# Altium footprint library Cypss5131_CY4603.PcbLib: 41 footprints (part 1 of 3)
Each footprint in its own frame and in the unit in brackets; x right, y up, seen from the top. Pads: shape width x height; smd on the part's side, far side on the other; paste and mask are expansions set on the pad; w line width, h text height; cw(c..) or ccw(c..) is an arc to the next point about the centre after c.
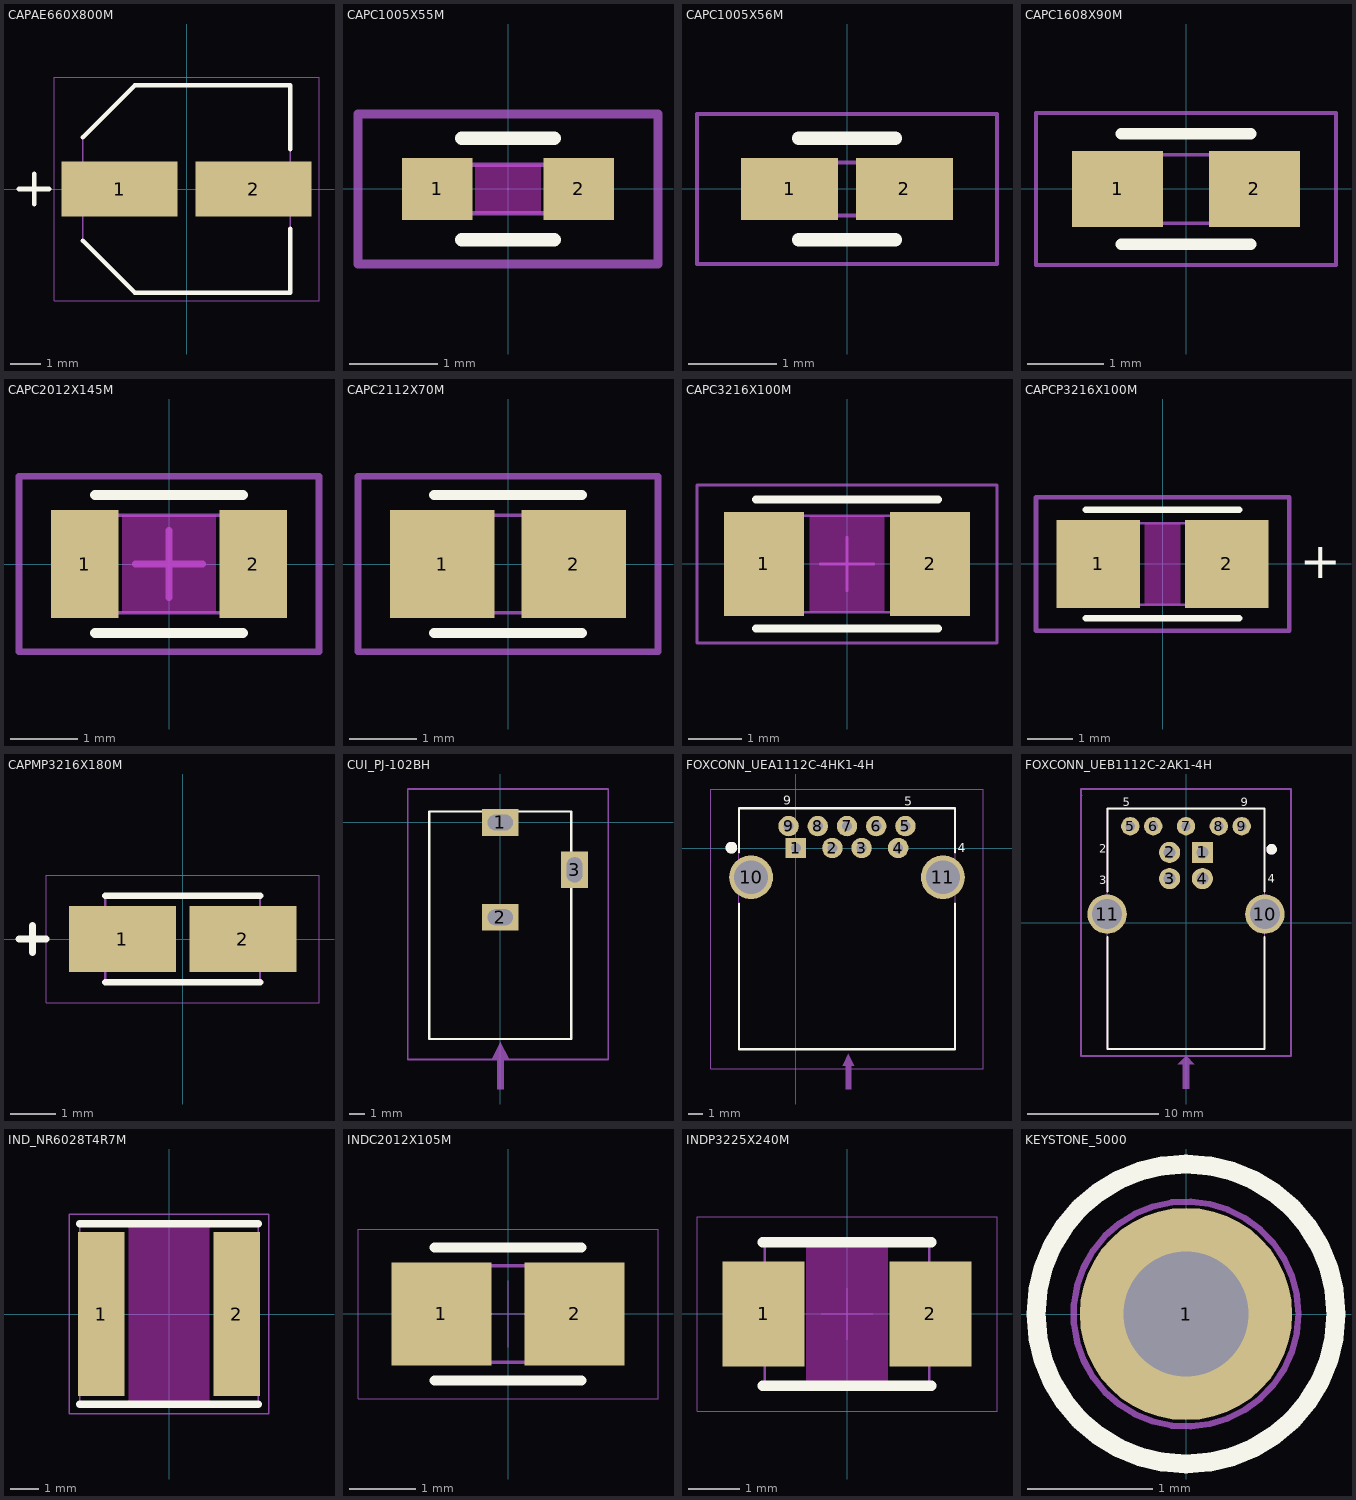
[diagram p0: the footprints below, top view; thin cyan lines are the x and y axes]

## CAPAE660X800M [mm]
height 8
pads (2):
  rect 3.8x1.8 smd mask+0: 1(-2.2,0) 2(2.2,0)
Top Overlay:
  lines w0.15: -5.5,0 -4.5,0 ; -5,-0.5 -5,0.5 ; -3.4,-1.7 -1.7,-3.4 -1.699,-3.401 3.401,-3.401 3.4,-3.4 3.4,-1.3 ; -3.4,1.7 -1.7,3.4 3.4,3.4 3.4,1.3
  text ".Designator" at -3.92,4.294 h0.8
Mechanical 13:
  lines w0.05: -3.4,-1.7 -1.7,-3.4 3.4,-3.4 3.4,3.4 -1.7,3.4 -3.4,1.7 -3.4,-1.7
  text ".Designator" at -4.142,-0.291 h0.8
Mechanical 14:
  text "R380_180" at -3.009,-5.076 h0.8
  text "CAPAE660X800M" at -5.4,5.9 h0.8
Mechanical 15:
  lines w0.01: -4.35,-3.675 -4.35,3.675 4.35,3.675 4.35,-3.675 -4.35,-3.675
3D body: height 8, standoff 0, extent -3.401,-3.401 3.401,3.401

## CAPC1005X55M [mm]
height 0.55
pads (2):
  rect 0.8x0.7 smd mask+0: 1(-0.8,0) 2(0.8,0)
Top Layer keep-out:
  rectangle: -0.375,-0.275 0.375,0.275
Top Overlay:
  lines w0.15: -0.525,-0.575 0.525,-0.575 ; -0.525,0.575 0.525,0.575
  text ".Designator" at -4.05,1.35 h0.8
Mechanical 13:
  lines w0.05: -0.525,-0.275 0.525,-0.275 0.525,0.275 -0.525,0.275 -0.525,-0.275
  text ".Designator" at -4.047,-0.16 h0.8
Mechanical 14:
  text "R80_70" at -2.25,-2 h0.8
  text "CAPC1005X55M" at -4.5,2.5 h0.8
Mechanical 15:
  lines w0.1: -1.7,-0.85 1.7,-0.85 1.7,0.85 -1.7,0.85 -1.7,-0.85
3D body: height 0.55, standoff 0, extent -0.525,-0.275 0.525,0.275

## CAPC1005X56M [mm]
height 0.56
pads (2):
  rect 1.1x0.7 smd mask+0: 1(-0.65,0) 2(0.65,0)
Top Overlay:
  lines w0.15: -0.55,-0.575 0.55,-0.575 ; -0.55,0.575 0.55,0.575
  text ".Designator" at -3.893,1.944 h0.8
Mechanical 13:
  lines w0.05: -0.55,-0.3 -0.55,0.3 0.55,0.3 0.55,-0.3 -0.55,-0.3
  text ".Designator" at -3.975,-0.137 h0.8
Mechanical 14:
  text "R70_110" at -2.709,-2.922 h0.8
  text "CAPC1005X56M" at -4.673,3.165 h0.8
Mechanical 15:
  lines w0.05: -1.7,-0.85 -1.7,0.85 1.7,0.85 1.7,-0.85 -1.7,-0.85
3D body: height 0.56, standoff 0, extent -0.55,-0.3 0.55,0.3

## CAPC1608X90M [mm]
height 0.9
pads (2):
  rect 1.2x1 smd mask+0: 1(-0.9,0) 2(0.9,0)
Top Overlay:
  lines w0.15: -0.85,-0.725 0.85,-0.725 ; -0.85,0.725 0.85,0.725
  text ".Designator" at -4.006,1.665 h0.8
Mechanical 13:
  lines w0.05: -0.85,-0.45 0.85,-0.45 0.85,0.45 -0.85,0.45 -0.85,-0.45
  text ".Designator" at -4.069,-0.185 h0.8
Mechanical 14:
  text "R100_120" at -2.883,-3.483 h0.8
  text "CAPC1608X90M" at -4.373,3.933 h0.8
Mechanical 15:
  lines w0.05: -1.975,-1 1.975,-1 1.975,1 -1.975,1 -1.975,-1
3D body: height 0.9, standoff 0, extent -0.85,-0.45 0.85,0.45

## CAPC2012X145M [mm]
height 1.45
pads (2):
  rect 1x1.6 smd mask+0: 1(-1.25,0) 2(1.25,0)
Top Layer keep-out:
  rectangle: -0.7,-0.725 0.7,0.725
Top Overlay:
  lines w0.15: -1.1,-1.025 1.1,-1.025 ; -1.1,1.025 1.1,1.025
  text ".Designator" at -4.094,1.821 h0.8
Mechanical 13:
  lines w0.05: -1.1,-0.725 -1.1,0.725 1.1,0.725 1.1,-0.725 -1.1,-0.725
  text ".Designator" at -4.101,0.004 h0.8
Mechanical 14:
  text "R100_160" at -2.677,-3.143 h0.8
  text "CAPC2012X145M" at -4.343,3.147 h0.8
Mechanical 15:
  lines w0.1: -0.5,0 0.5,0 ; 0,-0.5 0,0.5 ; -2.225,-1.3 -2.225,1.3 2.225,1.3 2.225,-1.3 -2.225,-1.3
3D body: height 1.45, standoff 0, extent -1.1,-0.725 1.1,0.725

## CAPC2112X70M [mm] "Chip Capacitor, 2-Leads, Body 2.0x1.3mm, IPC Low Density"
height 0.7
pads (2):
  rect 1.55x1.6 smd paste+0 mask+0: 1(-0.975,0)
  rect 1.55x1.6 smd mask+0: 2(0.975,0)
Top Overlay:
  lines w0.15: -1.1,-1.025 1.1,-1.025 ; -1.1,1.025 1.1,1.025
  text ".Designator" at -3.915,2.37 h0.8
Mechanical 13:
  lines w0.05: -1.1,-0.725 -1.1,0.725 1.1,0.725 1.1,-0.725 -1.1,-0.725
  text ".Designator" at -4.416,-0.259 h0.8
Mechanical 14:
  text "CAPC2112X70M" at -4.369,4.149 h0.8
  text "R160_155" at -2.566,-3.286 h0.8
Mechanical 15:
  lines w0.1: -2.225,-1.3 -2.225,1.3 2.225,1.3 2.225,-1.3 -2.225,-1.3
3D body: height 0.7, standoff 0, extent -1.1,-0.725 1.1,0.725

## CAPC3216X100M [mm]
height 1
pads (2):
  rect 1.5x1.95 smd mask+0: 1(-1.55,0) 2(1.55,0)
Top Layer keep-out:
  rectangle: -0.7,-0.9 0.7,0.9
Top Overlay:
  lines w0.15: -1.7,-1.2 1.7,-1.2 ; -1.7,1.2 1.7,1.2
  text ".Designator" at -4.105,2.041 h0.8
Mechanical 13:
  lines w0.05: -1.7,-0.9 1.7,-0.9 1.7,0.9 -1.7,0.9 -1.7,-0.9
  text ".Designator" at -4.227,-0.111 h0.8
Mechanical 14:
  text "R150_195" at -2.96,-3.101 h0.8
  text "CAPC3216X100M" at -4.883,3.3 h0.8
Mechanical 15:
  lines w0.05: -0.5,0 0.5,0 ; 0,-0.5 0,0.5 ; -2.8,-1.475 2.8,-1.475 2.8,1.475 -2.8,1.475 -2.8,-1.475
3D body: height 1, standoff 0, extent -1.7,-0.9 1.7,0.9

## CAPCP3216X100M [mm]
height 1
pads (2):
  rect 1.85x1.95 smd mask+0: 1(-1.425,0) 2(1.425,0)
Top Layer keep-out:
  rectangle: -0.4,-0.9 0.4,0.9
Top Overlay:
  lines w0.15: -1.7,-1.2 1.7,-1.2 ; -1.7,1.2 1.7,1.2
  text ".Designator" at -3.961,2.005 h0.8
  text "+" at 3.04,-0.315 h0.8
Mechanical 13:
  lines w0.05: -1.7,-0.9 -1.7,0.9 1.7,0.9 1.7,-0.9 -1.7,-0.9
  text ".Designator" at -3.978,-0.213 h0.8
  text "+" at 3.043,-0.318 h0.8
Mechanical 14:
  text "R185_195" at -3.005,-3.565 h0.8
  text "CAPCP3216X100M" at -5.122,3.327 h0.8
Mechanical 15:
  lines w0.1: -2.8,-1.475 -2.8,1.475 2.8,1.475 2.8,-1.475 -2.8,-1.475
3D body: height 1, standoff 0, extent -1.7,-0.9 1.7,0.9

## CAPMP3216X180M [mm] "Molded Capacitor, 2-Leads, Body 3.2x1.6mm, IPC Low Density"
height 1.8
pads (2):
  rect 2.35x1.45 smd mask+0: 1(-1.325,0) 2(1.325,0)
Top Overlay:
  lines w0.15: -1.7,-0.95 1.7,-0.95 ; -1.7,0.95 1.7,0.95
  lines w0.152: -3.6,0 -3,0 ; -3.3,-0.3 -3.3,0.3
  text ".Designator" at -3.931,1.915 h0.8
Mechanical 13:
  lines w0.05: -1.7,-0.9 -1.7,0.9 1.7,0.9 1.7,-0.9 -1.7,-0.9
  text ".Designator" at -3.988,-0.185 h0.8
Mechanical 14:
  text "R145_235" at -3.251,-2.677 h0.8
  text "CAPMP3216X180M" at -5.104,3.523 h0.8
Mechanical 15:
  lines w0.01: -3,-1.4 -3,1.4 3,1.4 3,-1.4 -3,-1.4
3D body: height 1.8, standoff 0, extent -1.7,-0.9 1.7,0.9

## CUI_PJ-102BH [mm]
height 11
pads (3):
  rect 2.3x1.7 hole 1 slot 1.6 at 0 deg mask+0: 1(0,0) 2(0,-6)
  rect 1.7x2.3 hole 1 slot 1.6 at 90 deg mask+0: 3(4.7,-3)
Top Overlay:
  lines w0.15: 4.5,-10.2 4.5,-3 ; -4.5,-13.7 -4.5,0.7 4.5,0.7 4.5,-13.7 -4.5,-13.7
  text ".Designator" at -3.997,2.804 h0.8
Mechanical 1:
  region: -0.195,-14.937 -0.189,-16.866 0.213,-16.866 0.205,-14.937 0.55,-14.931 0.012,-13.911 -0.518,-14.955
Mechanical 13:
  lines w0.05: -4.5,-13.7 4.5,-13.7 4.5,0.7 -4.5,0.7 -4.5,-13.7
  text ".Designator" at -3.997,-7.876 h0.8
Mechanical 14:
  text "R230_170H160_100" at -5.765,-18.172 h0.8
  text "CUI_PJ-102BH" at -4.355,4.236 h0.8
Mechanical 15:
  lines w0.1: -5.845,-15 6.82,-15 6.82,2.12 0,2.12 -5.845,2.12 -5.845,-15
3D body: height 11, standoff 0, extent -4.525,-13.725 4.525,0.725

## FOXCONN_UEA1112C-4HK1-4H [mm]
height 6.99
pads (11):
  rect 1.4x1.4 hole 0.7 mask+0: 1(0,0)
  round 1.4 hole 0.7 mask+0: 2(2.5,0) 3(4.5,0) 4(7,0) 5(7.5,1.5) 6(5.5,1.5) 7(3.5,1.5) 8(1.5,1.5) 9(-0.5,1.5)
  round 3 hole 2.3 mask+0: 10(-3.07,-2) 11(10.07,-2)
Top Overlay:
  circle w0.4: c-4.416,0.025 r0.2
  lines w0.15: -3.9,-3.81 -3.9,-13.78 10.896,-13.78 ; -3.9,-0.3 -3.9,2.72 ; -3.9,2.718 10.9,2.718 ; 10.898,-0.3 10.898,2.719 ; 10.9,-13.78 10.9,-3.81
  text "4" at 11.1,-0.279 h0.64
  text "5" at 7.417,2.896 h0.64
  text "9" at -0.864,2.946 h0.64
  text ".Designator" at -0.7,4.5 h0.8
Mechanical 1:
  region: 3.4,-14.9 3.4,-16.5 3.8,-16.5 3.8,-14.9 4,-14.9 3.6,-14.1 3.2,-14.9
Mechanical 13:
  circle w0.4: c-4.416,0.025 r0.2
  lines w0.05: -3.9,-13.78 -3.9,2.72 10.9,2.72 10.9,-13.78 -3.9,-13.78
  text ".Designator" at -0.001,-6.452 h0.8
Mechanical 14:
  text "C300H230" at 4.104,-18.901 h0.8
  text "S140H70" at 4.413,-17.597 h0.8
  text "C140H70" at 4.447,-16.328 h0.8
  text "FOXCONN_UEA1112C-4HK1-4H" at -5,6.1 h0.8
Mechanical 15:
  lines w0.05: -5.84,-15.1 12.84,-15.1 12.84,4.04 -5.84,4.04 -5.84,-15.1
3D body: height 6.99, standoff 0, extent -3.925,-13.805 10.925,2.745

## FOXCONN_UEB1112C-2AK1-4H [mm]
height 12.9
pads (11):
  rect 1.62x1.62 hole 0.92 mask+0: 1(1.25,5.353)
  round 1.62 hole 0.92 mask+0: 2(-1.25,5.353) 3(-1.25,3.353) 4(1.25,3.353)
  round 1.4 hole 0.7 mask+0: 5(-4.25,7.353) 6(-2.5,7.353) 7(0,7.353) 8(2.5,7.353) 9(4.25,7.353)
  round 3 hole 2.3 mask+0: 10(6.02,0.643) 11(-6.02,0.643)
Top Overlay:
  circle w0.4: c6.531,5.588 r0.2
  lines w0.15: -6,-1.082 -6,-9.657 6,-9.657 6,-1.082 ; -6,2.368 -6,8.693 6,8.693 6,2.368
  text "4" at 6.223,3.048 h0.64
  text "3" at -6.604,2.921 h0.64
  text "2" at -6.604,5.334 h0.64
  text "5" at -4.826,8.89 h0.64
  text "9" at 4.191,8.89 h0.64
  text ".Designator" at -3.048,9.017 h0.64
Mechanical 13:
  circle w0.4: c6.531,5.588 r0.2
  region: -0.635,-10.795 -0.254,-10.795 -0.254,-12.7 0.254,-12.7 0.254,-10.795 0.635,-10.795 0,-10.16
  lines w0.05: -6,-9.657 6,-9.657 6,8.693 -6,8.693 -6,-9.657
  text ".Designator" at -3.175,0.127 h0.64
Mechanical 14:
  text "FOXCONN_UEB1112C-2AK1-4H" at -7.366,10.922 h0.64
Mechanical 15:
  lines w0.152: -8.03,9.652 -7.972,9.71 ; -8.03,10.192 -8.03,-10.192 8.03,-10.192 8.03,10.192 -7.972,10.192
Mechanical 20:
  text "S140H70" at -2.383,-10.974 h0.64
  text "C140H70" at -2.421,-12.33 h0.64
  text "C162H92" at -2.384,-13.65 h0.64
  text "C300H230" at -2.7,-15.043 h0.64
  text "FOXCONN_UEB1112C-2AK1-4H" at -7.246,11.75 h0.64
3D body: height 12.9, standoff 0, extent -5.999,-9.656 5.999,8.692

## IND_NR6028T4R7M [mm]
height 2.8
pads (2):
  rect 1.6x5.7 smd mask+0: 1(-2.35,0) 2(2.35,0)
Top Layer keep-out:
  rectangle: -1.4,-3.1 1.4,3.1
Top Overlay:
  lines w0.254: -3.1,-3.127 3.1,-3.127 ; -3.1,3.127 3.1,3.127
  text ".Designator" at -3.94,4.253 h0.8
Mechanical 13:
  lines w0.05: -3.1,-3.1 -3.1,3.1 3.1,3.1 3.1,-3.1 -3.1,-3.1
  text ".Designator" at -4.452,-0.208 h0.8
Mechanical 14:
  text "R160_570" at -3.122,-4.636 h0.8
  text "IND_NR6028T4R7M" at -5.574,5.604 h0.8
Mechanical 15:
  lines w0.05: -3.45,-3.45 3.45,-3.45 3.45,3.45 -3.45,3.45 -3.45,-3.45
3D body: height 2.8, standoff 0, extent -3.125,-3.125 3.125,3.125

## INDC2012X105M [mm] "Chip Resistor, 2-Leads, Body 2.0x1.3mm, IPC Low Density"
height 1.05
pads (2):
  rect 1.5x1.55 smd mask+0: 1(-1,0) 2(1,0)
Top Overlay:
  lines w0.15: -1.1,-1 1.1,-1 ; -1.1,1 1.1,1
  text ".Designator" at -4.219,1.87 h0.8
Mechanical 13:
  lines w0.05: -1.1,-0.725 -1.1,0.725 1.1,0.725 1.1,-0.725 -1.1,-0.725
  text ".Designator" at -4.164,-0.099 h0.8
Mechanical 14:
  text "INDC2012X105M" at -4.672,3.526 h0.8
  text "R155_150" at -2.865,-2.949 h0.8
Mechanical 15:
  lines w0.01: -0.5,0 0.5,0 ; 0,-0.5 0,0.5 ; -2.25,-1.275 -2.25,1.275 2.25,1.275 2.25,-1.275 -2.25,-1.275
3D body: height 1.05, standoff 0, extent -1.1,-0.725 1.1,0.725

## INDP3225X240M [mm]
height 2.4
pads (2):
  rect 1.6x2.05 smd mask+0: 1(-1.625,0) 2(1.625,0)
Top Layer keep-out:
  rectangle: -0.8,-1.4 0.8,1.35
Top Overlay:
  lines w0.2: -1.65,-1.4 1.65,-1.4 ; -1.65,1.4 1.65,1.4
  text ".Designator" at -4.059,2.446 h0.8
Mechanical 13:
  lines w0.05: -1.6,-1.35 -1.6,1.35 1.6,1.35 1.6,-1.35 -1.6,-1.35
  text ".Designator" at -4.219,-0.195 h0.8
Mechanical 14:
  text "INDP3225X240M" at -4.649,3.854 h0.8
  text "R205_160" at -2.848,-3.248 h0.8
Mechanical 15:
  lines w0.01: -0.5,0 0.5,0 ; 0,-0.5 0,0.5 ; -2.925,-1.9 -2.925,1.9 2.925,1.9 2.925,-1.9 -2.925,-1.9
3D body: height 2.4, standoff 0, extent -1.6,-1.35 1.6,1.35

## KEYSTONE_5000 [mm]
height 4.572
pads (1):
  round 1.7 hole 1 mask+0: 1(0,0)
Top Overlay:
  circle w0.152: c0,0 r1.2
  text ".Designator" at -3.325,1.792 h0.64
Mechanical 13:
  circle w0.051: c0,0 r0.9
  text ".Designator" at -3.263,-0.11 h0.64
Mechanical 14:
  text "C170H100" at -3.203,-2.501 h0.8
  text "KEYSTONE_5000" at -4.793,2.873 h0.8
3D body: height 4.57, standoff 0, extent -0.907,-0.907 0.907,0.907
